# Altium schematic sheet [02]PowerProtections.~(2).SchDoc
size A4; SheetNumber: 2; SheetTotal: 5
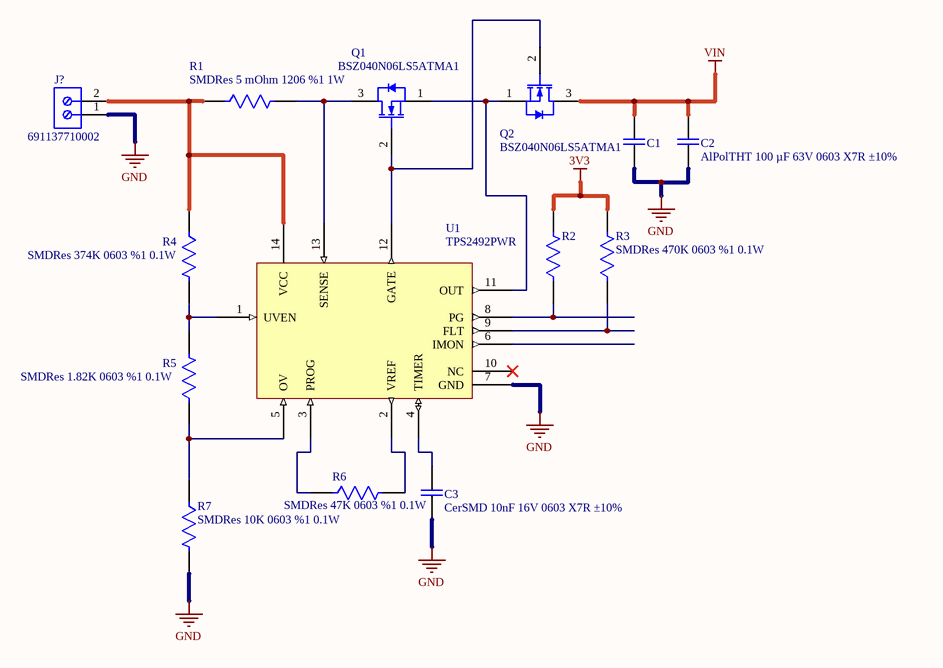
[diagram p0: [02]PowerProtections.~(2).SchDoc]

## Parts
C1  AlPolTHT 100 µF 63V 0603 X7R ±10%  [107AVG063MFBJ]  (value not drawn)
C2  AlPolTHT 100 µF 63V 0603 X7R ±10%  [107AVG063MFBJ]
C3  CerSMD 10nF 16V 0603 X7R ±10%  [CAPC1608X09N]
J?  691137710002  [691137710002]
Q1  BSZ040N06LS5ATMA1  [PG-TSDSON-8-FL]
Q2  BSZ040N06LS5ATMA1  [PG-TSDSON-8-FL]
R1  SMDRes 5 mOhm 1206 %1 1W  [RESC3116X10N]
R2  SMDRes 470K 0603 %1 0.1W  [RESC1508X06N]  (value not drawn)
R3  SMDRes 470K 0603 %1 0.1W  [RESC1508X06N]
R4  SMDRes 374K 0603 %1 0.1W  [RESC1508X06N]
R5  SMDRes 1.82K 0603 %1 0.1W  [RESC1508X06N]
R6  SMDRes 47K 0603 %1 0.1W  [RESC1508X06N]
R7  SMDRes 10K 0603 %1 0.1W  [RESC1508X06N]
U1  TPS2492PWR  [TSOP65P640X120-14L]

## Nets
3V3: R2.2 R3.2
GND: C1.2 C2.2 C3.2 J?.1 R7.2 U1.7(GND)
VIN: C1.1 C2.1 Q2.3(D)
NetC3_1: C3.1 U1.4(TIMER)
NetJ?_2: J?.2 R1.1 R4.1 U1.14(VCC)
NetQ1_1: Q1.1(S) Q2.1(S) U1.11(OUT)
NetQ1_2: Q1.2(G) Q2.2(G) U1.12(GATE)
NetQ1_3: Q1.3(D) R1.2 U1.13(SENSE)
NetR2_1: R2.1 U1.8(PG)
NetR3_1: R3.1 U1.9(FLT)
NetR4_2: R4.2 R5.2 U1.1(UVEN)
NetR5_1: R5.1 R7.1 U1.5(OV)
NetR6_1: R6.1 U1.3(PROG)
NetR6_2: R6.2 U1.2(VREF)

Not connected (* = marked no-connect by the designer): U1 6(IMON) 10(NC)*

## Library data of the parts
C1 C2 = CMP-00002-4: Ceramic Capacitor SMD 100 µF 63V 0603 X7R ±10%; Manufacturer: Cornell Dubilier Knowles
C3 = CMP-00001-3: Ceramic Capacitor SMD  10nF 16V 0603 X7R ±10%; Manufacturer Number: CL10B103KO8WPNC; Manufacturer: Samsung Electro-Mechanics
J? = CMP-00022-1: würth terminal
Q1 Q2 = CMP-00004-1: N-MOS 60V 17A (Ta) 101A (Tc)
R1 = CMP-00007-2: 5 mOhms ±1% 1W Chip Resistor 1206 (3216 Metric) Automotive AEC-Q200, Current Sense, Moisture Resistant Metal Foil; Manufacturer Number: CSRF1206FT5L00; Manufacturer: Stackpole Electronics Inc
R2 R3 = CMP-00006-1: Res Thick Film 0603 470K Ohm 1% 0.1W(1/10W) ±100ppm/C Pad SMD T/R Automotive AEC-Q200; Manufacturer: Stackpole Electronics Inc; Manufacturer Number: RMCF0603FT470K
R4 = CMP-00005-2: Res Thick Film 0603 374K Ohm 1% 0.1W(1/10W) ±100ppm/C Pad SMD T/R Automotive AEC-Q200; Manufacturer: Stackpole Electronics Inc; Manufacturer Number: RMCF0603FT374K
R5 = CMP-00003-2: Res Thick Film 0603 1.82K Ohm 1% 0.1W(1/10W) ±100ppm/C Pad SMD T/R Automotive AEC-Q200; Manufacturer: Stackpole Electronics Inc; Manufacturer Number: RMCF0603FT1K82
R6 = CMP-00008-1: Res Thick Film 0603 47K Ohm 1% 0.1W(1/10W) ±100ppm/C Pad SMD T/R Automotive AEC-Q200; Manufacturer Number: RMCF0603FT47K0; Manufacturer: Stackpole Electronics Inc
R7 = CMP-00001-1-1: Res Thick Film 0603 10K Ohm 1% 0.1W(1/10W) ±100ppm/C Pad SMD T/R Automotive AEC-Q200; Manufacturer Number: RMCF0603FT10K0; Manufacturer: Stackpole Electronics Inc
U1 = CMP-00000-1: eFuses - External MOSFETs - 9V-80V; Manufacturer: Texas Instruments; Temperature Rating: -40°C up to 125°C; Voltage Rating: 9V up to 80V; Internal Switch(s): No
